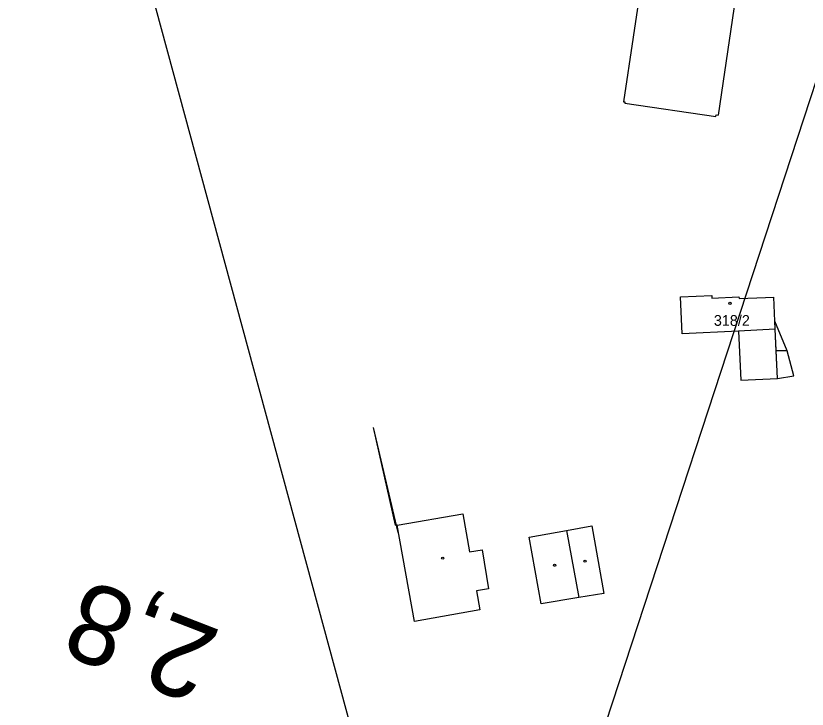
# Model space of a CAD drawing. Extents: x -728802 to -728097, y -1073200 to -1072700.
# Drawn here: x -728571.2 to -728446.1, y -1072982.9 to -1072873.2 of the extents above; entities that cross this region are included whole.
import ezdxf

# ---------------------------------------------------------------- set-up
doc = ezdxf.new("R2010")
doc.units = 0
for name, color, linetype in [('A5_JŽM', 7, 'Continuous'), ('Hranice parcel', 7, 'Continuous'), ('ZZZ_popisky', 7, 'Continuous')]:
    doc.layers.add(name, color=color, linetype=linetype)

msp = doc.modelspace()

# ---------------------------------------------------------------- linework, layer by layer
at = {"layer": 'Hranice parcel'}
for p, q in [((-728455.28, -1072856.27), (-728460.15, -1072888.97)), ((-728466.12, -1072917.7), (-728461.16, -1072917.51)), ((-728465.84, -1072923.57), (-728466.12, -1072917.7)), ((-728461.16, -1072917.51), (-728461.12, -1072917.92)), ((-728461.12, -1072917.92), (-728456.85, -1072917.69)), ((-728456.85, -1072917.69), (-728456.84, -1072917.97)), ((-728456.84, -1072917.97), (-728452.67, -1072917.79)), ((-728452.67, -1072917.79), (-728451.33, -1072917.73)), ((-728451.16, -1072921.53), (-728451.33, -1072917.73)), ((-728449.25, -1072926.26), (-728451.16, -1072921.53)), ((-728451.1, -1072922.84), (-728451.16, -1072921.53)), ((-728456.95, -1072923.13), (-728465.84, -1072923.57)), ((-728451.1, -1072922.84), (-728456.95, -1072923.13)), ((-728456.95, -1072923.13), (-728456.55, -1072930.88)), ((-728450.94, -1072926.26), (-728451.1, -1072922.84)), ((-728450.74, -1072930.6), (-728451.1, -1072922.84)), ((-728449.25, -1072926.26), (-728450.94, -1072926.26)), ((-728450.74, -1072930.6), (-728450.94, -1072926.26)), ((-728448.15, -1072930.18), (-728449.25, -1072926.26)), ((-728456.55, -1072930.88), (-728450.74, -1072930.6)), ((-728450.74, -1072930.6), (-728448.15, -1072930.18)), ((-728514.74, -1072938.38), (-728511.25, -1072953.81)), ((-728514.74, -1072938.38), (-728510.81, -1072954.97)), ((-728510.91, -1072953.81), (-728500.55, -1072952.01)), ((-728500.55, -1072952.01), (-728499.48, -1072958.02)), ((-728510.91, -1072953.81), (-728511.25, -1072953.81)), ((-728508.16, -1072969.07), (-728510.91, -1072953.81)), ((-728490.04, -1072955.73), (-728484.11, -1072954.67)), ((-728484.11, -1072954.67), (-728480.14, -1072953.95)), ((-728484.11, -1072954.67), (-728482.2, -1072965.27)), ((-728480.14, -1072953.95), (-728478.24, -1072964.61)), ((-728488.14, -1072966.25), (-728490.04, -1072955.73)), ((-728499.48, -1072958.02), (-728497.5, -1072957.71)), ((-728497.5, -1072957.71), (-728496.46, -1072963.88)), ((-728496.46, -1072963.88), (-728498.37, -1072964.2)), ((-728498.37, -1072964.2), (-728497.86, -1072967.24)), ((-728478.24, -1072964.61), (-728482.2, -1072965.27)), ((-728482.2, -1072965.27), (-728488.14, -1072966.25)), ((-728497.86, -1072967.24), (-728508.16, -1072969.07))]:
    msp.add_line(p, q, dxfattribs=at)
for points in [[(-728459.04, -1072836.7), (-728467.13, -1072835.48), (-728467.16, -1072835.65), (-728467.45, -1072835.63), (-728475.14, -1072886.87)], [(-728475.14, -1072886.87), (-728474.88, -1072886.88), (-728474.89, -1072887.04), (-728460.51, -1072889.16), (-728460.48, -1072888.91), (-728460.15, -1072888.97)]]:
    msp.add_lwpolyline(points, dxfattribs=at)
for centre in [(-728458.27, -1072918.74), (-728503.72, -1072959.05), (-728481.2, -1072959.52), (-728486.01, -1072960.16)]:
    msp.add_circle(centre, 0.175, dxfattribs=at)
at = {"layer": 'ZZZ_popisky'}
for points in [[(-728496.07, -1073040.51), (-728413.22, -1072787.63), (-728463.11, -1072771.29)], [(-728504.21, -1073037.38), (-728573.95, -1072780.58), (-728624.61, -1072794.34)]]:
    msp.add_lwpolyline(points, dxfattribs=at)

# ---------------------------------------------------------------- texts
at = {"layer": 'A5_JŽM'}
msp.add_text('2,8', height=12.5, rotation=158.8151, dxfattribs=at).set_placement((-728538.48, -1072970.63))
at = {"layer": 'Hranice parcel'}
msp.add_text('318/2', height=1.7, dxfattribs=at).set_placement((-728460.82, -1072922.29))

doc.saveas('drawing.dxf')
